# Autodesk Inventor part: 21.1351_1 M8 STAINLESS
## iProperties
Created: 2006-12
Part Number: 21.1351_1 M8 STAINLESS
Document SubType Name: Modeling
Designer: Andy Moles
Material: Stainless Steel
Density: 8.08 g/cm^3
Author: Andy Moles
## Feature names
1. Extrusion1
2. Revolution1
